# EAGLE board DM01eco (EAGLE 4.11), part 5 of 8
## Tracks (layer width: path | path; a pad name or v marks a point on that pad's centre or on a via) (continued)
DATA_OUT  (via drill 0.61) (continued)
  Bottom 0.152: v22.86,142.24 21.59,143.51 19.68,143.51 1.91,161.29 1.91,164.47 B32.R2 | v250.82,289.56 252.73,289.56 255.91,286.38 259.71,290.19 v270.51,279.4
DATA_OUT0  (via drill 0.61)
  Top 0.152: v10.16,97.79 15.88,103.51 15.88,108.59 17.14,109.86 17.14,110.49 26.67,120.02 26.67,123.19 C30.F2 | v254.63,1.27 269.24,1.27 270.51,2.54 276.86,2.54 307.98,33.66 307.98,36.2 309.25,37.47 D08.M2
  Route2 0.152: v100.33,6.35 104.78,1.91 v132.08,29.21 | v164.47,1.91 165.74,3.18 173.35,3.18 173.99,3.81 187.96,3.81 190.5,1.27 193.68,1.27 194.94,2.54 198.12,2.54 198.75,3.18 200.03,3.18 201.93,5.08 216.53,5.08 218.44,3.18 219.07,3.81 222.88,3.81 226.69,7.62 229.24,7.62 234.31,12.7 235.59,12.7 v236.85,13.97
  Bottom 0.152: v10.16,97.79 7.62,95.25 15.88,87 15.88,80.65 41.27,55.24 41.27,36.2 60.33,17.14 67.31,17.14 70.48,13.97 81.92,13.97 83.19,12.7 93.98,12.7 v100.33,6.35 | v132.08,29.21 132.08,28.58 146.69,13.97 149.86,13.97 154.94,8.89 156.21,8.89 163.19,1.91 v164.47,1.91 | v236.85,13.97 240.03,13.97 252.09,1.91 254,1.91 v254.63,1.27
DATA_OUT1  (via drill 0.61)
  Top 0.152: v241.3,40.64 239.4,40.64 203.2,4.45 203.2,3.81 201.93,2.54 199.39,2.54 v198.75,1.91 | v130.18,41.27 130.18,46.99 v133.35,50.16 | v45.09,133.98 42.55,136.53 27.94,121.92 27.94,118.75 27.3,118.11 C30.J2
  Route15 0.152: v241.3,40.64 243.21,38.73 245.75,38.73 D13.M2 | v198.75,1.91 196.85,1.91 196.22,2.54 191.77,2.54 190.5,1.27 180.34,1.27 179.07,2.54 175.26,2.54 173.99,3.81 168.91,3.81 148.59,24.13 142.88,24.13 132.72,34.29 132.72,34.92 130.18,37.47 v130.18,41.27 | v133.35,50.16 133.35,52.07 123.19,62.23 117.47,62.23 87.63,92.08 87,92.08 v45.09,133.98
DATA_OUT2  (via drill 0.61)
  Top 0.152: v92.08,30.48 95.89,30.48 99.06,33.66 107.31,33.66 108.58,32.38 v109.22,33.02
  Route2 0.152: v132.08,6.35 142.88,6.35 146.05,9.53 151.13,9.53 158.12,16.51 158.12,17.78 160.66,20.32 161.29,20.32 175.26,34.29 176.53,34.29 178.44,36.2 180.97,36.2 182.25,37.47 D18.M2
  Route15 0.152: v57.78,64.77 v92.08,30.48
  Bottom 0.152: v57.78,64.77 49.53,73.03 49.53,78.11 40.64,87 35.56,87 20.95,101.6 26.67,107.32 26.67,110.49 C30.L2 | v109.22,33.02 109.22,32.38 111.76,29.84 116.84,29.84 120.65,26.04 120.65,22.86 119.38,21.59 124.46,16.51 124.46,13.97 v132.08,6.35
DATA_OUT3  (via drill 0.61)
  Top 0.152: v67.94,65.41 67.94,66.04 73.66,71.75 79.38,71.75 v80.01,72.39
  Route15 0.152: v80.01,72.39 81.28,72.39 111.12,42.55 112.39,42.55 114.94,40.01 117.47,40.01 118.75,38.73 D23.M2
  Bottom 0.152: v67.94,65.41 64.14,65.41 63.5,66.04 62.87,66.04 41.27,87.63 41.27,93.34 34.29,100.33 29.21,100.33 27.3,102.23 27.3,104.14 C30.N2
DATA_OUT4  (via drill 0.61)
  Top 0.152: v14.61,81.92 14.61,83.19 26.04,94.62 26.04,97.16 26.67,97.79 C30.R2
  Route15 0.152: v14.61,81.92 55.24,41.27 55.24,38.73 D28.M2
DATA_OUT5  (via drill 0.61)
  Top 0.152: v3.17,136.53 3.17,157.48 15.88,170.18 15.88,175.9 50.16,210.19 50.16,214.63 v55.88,220.34 | v100.33,240.66 102.23,242.57 104.78,242.57 106.05,243.84 A24.M2
  Route2 0.152: v55.88,220.34 54.61,221.62 85.72,252.73 88.27,252.73 v88.9,253.37
  Route15 0.152: v3.17,136.53 3.17,119.38 26.67,95.89 26.67,92.71 C30.T2
  Bottom 0.152: v88.9,253.37 88.9,252.09 v100.33,240.66
DATA_OUT6  (via drill 0.61)
  Top 0.152: v3.17,117.48 3.17,122.56 17.14,136.53 17.78,136.53 21.59,140.34 21.59,142.88 27.94,149.22 33.02,149.22 39.37,155.58 39.37,156.21 41.27,158.12 41.27,163.19 62.23,184.15 v62.87,184.15
  Route15 0.152: v62.87,184.15 62.23,184.15 43.81,202.56 43.81,203.84 53.34,213.36 53.34,216.53 50.8,219.08 50.8,224.79 55.24,229.24 43.81,240.66 43.81,243.21 43.18,243.84 A29.M2
  Bottom 0.152: v3.17,117.48 3.17,113.03 26.67,89.54 26.67,86.36 C30.V2
DB0  (via drill 0.61)
  Top 0.152: v176.53,271.78 183.51,271.78 185.42,269.88 187.96,272.41 189.23,272.41 191.13,274.32 196.22,274.32 200.66,278.76 201.93,278.76 210.82,287.65 213.36,287.65 215.26,289.56 216.53,289.56 v217.17,290.19
  Route2 0.152: v81.28,195.58 81.28,196.85 92.08,207.65 93.98,207.65 100.97,214.63 102.87,214.63 107.95,219.71 116.2,219.71 155.57,259.08 156.21,259.08 162.56,265.43 168.91,265.43 175.26,271.78 v176.53,271.78
  Route15 0.152: v81.28,195.58 81.92,195.58 90.17,187.33 90.17,184.78 B25.J2 | v217.17,290.19 218.44,290.19 219.07,289.56 244.47,289.56 245.11,288.92 250.19,288.92 250.82,288.29 254,288.29 255.91,286.38 257.18,286.38 257.81,285.75 269.24,285.75 271.78,283.21 273.05,283.21 278.13,278.13 279.4,278.13 289.56,267.97 292.74,267.97 293.37,267.33 A09.D2
DB0-0  (via drill 0.61)
  Top 0.152: v274.32,80.01 271.78,80.01 v255.27,63.5
  Route15 0.152: v231.78,85.73 231.78,87 217.81,100.97 217.81,101.6 215.9,103.51 214.63,103.51 212.72,105.41 212.72,106.05 196.85,121.92 193.68,121.92 192.41,123.19 C17.F2
  Bottom 0.152: v274.32,80.01 281.31,73.03 283.21,73.03 285.75,70.48 285.75,69.85 287.02,68.58 288.29,68.58 293.37,63.5 293.37,60.96 D09.D2 | v255.27,63.5 247.65,71.12 246.38,71.12 v231.78,85.73
DB0-1  (via drill 0.61)
  Top 0.152: v237.49,69.85 236.85,69.85 231.78,64.77 231.78,62.23 230.5,60.96 D14.D2
  Route2 0.152: v203.2,104.78 201.93,103.51 200.66,103.51 198.12,100.97 196.22,102.87 196.22,104.78 196.85,105.41 196.85,106.68 203.2,113.03 203.2,113.67 207.01,117.48 205.74,118.75 203.84,118.75 201.93,116.84 200.66,116.84 198.12,114.3 195.58,116.84 192.41,116.84 C17.J2
  Route15 0.152: v203.2,104.78 203.2,103.51 232.41,74.3 233.04,74.3 v237.49,69.85
DB0-2  (via drill 0.61)
  Top 0.152: v201.29,98.43 v165.74,62.87 | v190.5,109.22 191.77,110.49 C17.L2
  Route15 0.152: v165.74,62.87 166.37,62.23 166.37,60.96 D19.D2
  Bottom 0.152: v190.5,109.22 v201.29,98.43
DB0-3  (via drill 0.61)
  Top 0.152: v155.57,79.38 158.75,82.55 166.37,82.55 180.97,97.16 180.97,97.79 182.25,99.06 183.51,99.06 187.96,103.51 191.13,103.51 191.77,104.14 C17.N2
  Route2 0.152: v114.94,45.72 116.2,45.72 117.47,46.99 117.47,52.7 133.35,68.58 133.35,73.03 144.15,83.82 149.22,83.82 v149.86,84.46
  Bottom 0.152: v114.94,45.72 103.5,57.15 103.5,59.69 D24.D2 | v149.86,84.46 150.5,84.46 v155.57,79.38
DB0-4  (via drill 0.61)
  Top 0.152: v99.69,12.7 109.86,12.7 130.81,33.66 131.44,33.66 133.35,35.56 133.35,36.2 v146.69,49.53
  Route2 0.152: v146.69,49.53 152.4,55.24 153.03,55.24 154.31,56.52 154.31,58.42 155.57,59.69 155.57,65.41 187.32,97.16 191.13,97.16 191.77,97.79 C17.R2
  Route15 0.152: v99.69,12.7 99.06,13.34 95.89,13.34 72.39,36.83 66.67,36.83 43.81,59.69 40.01,59.69 D29.D2
DB0-5  (via drill 0.61)
  Top 0.152: v206.38,133.35 206.38,142.88 v207.65,144.15
  Route2 0.152: v215.26,111.12 214.63,111.12 209.55,106.05 209.55,105.41 201.29,97.16 200.66,97.16 196.22,92.71 192.41,92.71 C17.T2
  Route15 0.152: v189.23,163.83 189.23,164.47 186.69,167 185.42,167 184.15,168.28 184.15,170.81 180.97,173.99 179.71,173.99 155.57,198.12 155.57,205.11 154.94,205.74 154.94,210.82 142.24,223.52 137.16,223.52 98.42,262.25 97.16,262.25 94.61,264.8 92.08,264.8 90.81,266.06 A25.D2
  Bottom 0.152: v215.26,111.12 216.53,112.4 217.17,112.4 218.44,113.67 217.17,114.94 217.17,115.57 215.9,116.84 215.9,117.48 214.63,118.75 213.36,118.75 208.28,123.83 207.65,123.83 206.38,125.09 v206.38,133.35 | v207.65,144.15 207.65,146.05 189.87,163.83 v189.23,163.83
DB0-6  (via drill 0.61)
  Route15 0.152: v142.88,139.7 142.88,137.8 175.26,105.41 176.53,105.41 179.71,102.23 179.71,101.6 188.59,92.71 189.23,92.71 v190.5,91.44
  Bottom 0.152: v142.88,139.7 136.53,146.05 136.53,147.32 130.18,153.67 130.18,159.39 128.91,160.66 128.91,161.29 96.52,193.68 96.52,194.31 53.98,236.86 53.98,242.57 30.48,266.06 27.3,266.06 A30.D2 | v190.5,91.44 190.5,89.54 191.13,88.9 191.13,87 191.77,86.36 C17.V2
DB1  (via drill 0.61)
  Top 0.152: v220.98,267.33 221.62,267.33 226.06,271.78 232.41,271.78 233.04,271.14 238.12,271.14 238.76,271.78 243.84,271.78 247.65,275.59 247.65,276.86 v257.81,287.02 | v287.65,258.44 288.93,258.44 289.56,259.08 294.64,259.08 295.27,259.71 295.27,260.99 297.18,262.89 A09.E2
  Route2 0.152: v182.25,252.73 181.61,252.73 160.66,231.78 160.02,231.78 148.59,220.34 142.88,220.34 131.44,208.91 128.27,208.91 127.64,208.28 124.46,208.28 111.12,194.94 111.12,194.31 109.86,193.04 109.22,193.04 94.61,178.44 90.81,178.44 B25.L2 | v190.5,245.75 199.39,245.75 v220.98,267.33
  Bottom 0.152: v182.25,252.73 183.51,252.73 v190.5,245.75 | v257.81,287.02 258.44,287.02 273.05,272.41 273.05,271.78 286.38,258.44 v287.65,258.44
DB1-0  (via drill 0.61)
  Top 0.152: v292.1,53.98 292.1,54.61 294,56.52 296.55,56.52 D09.E2
  Route2 0.152: v231.78,116.84 231.78,118.11 229.87,120.02 227.97,118.11 226.06,118.11 223.52,120.65 222.25,119.38 219.07,119.38 215.26,123.19 214.63,122.56 212.72,122.56 205.1,114.94 205.1,113.67 203.2,111.76 203.2,109.22 204.47,107.95 199.39,102.87 v198.12,102.87
  Route15 0.152: v292.1,53.98 290.83,53.98 275.59,69.22 275.59,73.03 264.8,83.82 260.99,83.82 254.63,90.17 254.63,90.81 253.37,92.08 252.09,92.08 244.47,99.7 238.76,99.7 231.78,106.68 231.78,112.4 232.41,113.03 231.78,113.67 v231.78,116.84
  Bottom 0.152: v198.12,102.87 197.49,102.87 191.77,108.59 191.77,109.22 188.59,112.4 187.96,112.4 180.97,119.38 180.97,121.92 179.71,123.19 C18.F2
DB1-1  (via drill 0.61)
  Top 0.152: v203.84,80.01 203.84,80.65 v208.28,85.09
  Route2 0.152: v231.78,55.24 233.04,56.52 D14.E2
  Bottom 0.152: v231.78,55.24 215.26,71.75 210.19,71.75 204.47,77.47 204.47,79.38 v203.84,80.01 | v208.28,85.09 208.28,85.73 190.5,103.51 189.87,103.51 184.78,108.59 184.15,108.59 182.88,109.86 182.88,111.76 180.97,113.67 180.97,115.57 179.71,116.84 C18.J2
DB1-2  (via drill 0.61)
  Top 0.152: v189.87,78.11 189.23,77.47 189.23,75.57 184.78,71.12 180.97,71.12 173.35,63.5 172.09,63.5 170.18,61.59 170.18,57.78 D19.E2 | v170.18,98.43 170.18,99.06 178.44,107.32 178.44,109.86 179.07,110.49 C18.L2
  Route15 0.152: v189.87,78.11 184.15,83.82 184.15,85.09 v183.51,85.73
  Bottom 0.152: v183.51,85.73 182.88,85.73 v170.18,98.43
DB1-3  (via drill 0.61)
  Top 0.152: v114.3,66.67 113.03,65.41 111.76,65.41 107.31,60.96 107.31,59.05 106.68,58.42 106.68,57.78 D24.E2 | v114.3,77.47 114.3,80.65 124.46,90.81 129.54,90.81 133.35,94.62 133.35,97.16 132.08,98.43 142.88,109.22 148.59,109.22 v153.03,113.67
  Route2 0.152: v168.91,103.51 172.09,106.68 174.62,106.68 177.8,103.51 179.07,104.78 C18.N2
  Route15 0.152: v114.3,66.67 114.3,68.58 118.75,73.03 v114.3,77.47
  Bottom 0.152: v153.03,113.67 154.94,113.67 165.1,103.51 v168.91,103.51
DB1-4  (via drill 0.61)
  Top 0.152: v78.11,78.11 78.11,77.47 66.04,65.41 66.04,64.77 45.72,44.45 41.27,48.89 41.27,51.43 42.55,52.7 42.55,56.52 D29.E2 | v109.86,49.53 109.86,50.8 111.76,52.7 117.47,52.7 133.35,68.58 133.35,73.03 144.15,83.82 149.22,83.82 152.4,80.65 162.56,90.81 168.91,90.81 175.26,97.16 178.44,97.16 179.07,97.79 C18.R2
  Route15 0.152: v78.11,78.11 82.55,78.11 100.97,59.69 101.6,59.69 107.95,53.34 107.95,51.43 v109.86,49.53
DB1-5  (via drill 0.61)
  Route2 0.152: v106.68,166.37 107.31,166.37 117.47,176.53 117.47,179.71 116.2,180.97 142.24,207.01 142.24,209.55 v138.43,213.36
  Route15 0.152: v106.68,166.37 107.31,165.74 107.31,164.47 118.75,153.03 118.75,151.13 130.18,139.7 130.18,138.43 134.62,133.98 134.62,133.35 165.1,102.87 165.1,102.23 170.18,97.16 170.81,97.16 175.26,92.71 179.07,92.71 C18.T2 | v138.43,213.36 134.62,213.36 117.47,230.5 117.47,236.86 94.61,259.71 94.61,262.25 93.98,262.89 A25.E2
DB1-6  (via drill 0.61)
  Top 0.152: v155.57,116.84 155.57,123.19 v157.48,125.09
  Route2 0.152: v183.51,92.08 179.71,88.27 179.71,86.36 C18.V2
  Route15 0.152: v183.51,92.08 182.25,92.08 177.16,97.16 176.53,97.16 174.62,99.06 174.62,99.7 173.99,100.33 168.28,100.33 155.57,113.03 v155.57,116.84 | v157.48,125.09 156.21,125.09 145.41,135.89 145.41,138.43 146.69,139.7 145.41,140.97 143.51,140.97 111.12,173.36 111.12,173.99 109.22,175.9 108.58,175.9 104.78,179.71 104.78,180.34 99.69,185.42 99.06,185.42 95.25,189.23 95.25,189.87 87,198.12 86.36,198.12 81.92,202.56 81.92,205.11 83.19,206.38 63.5,226.06 63.5,226.69 31.75,258.44 31.75,259.71 31.11,260.35 31.11,262.25 30.48,262.89 A30.E2
DB2  (via drill 0.61)
  Top 0.152: v236.85,278.13 246.38,278.13 v255.91,287.65
  Route2 0.152: v236.85,278.13 226.06,278.13 222.25,274.32 216.53,274.32 214.63,272.41 213.36,272.41 212.09,271.14 211.46,271.14 205.1,264.8 205.1,264.16 193.68,252.73 187.32,252.73 163.19,228.6 161.29,230.5 159.38,230.5 148.59,219.71 142.88,219.71 128.27,205.11 127.64,205.11 111.12,188.59 105.41,188.59 104.78,187.96 104.78,182.88 93.98,172.09 90.81,172.09 B25.N2
  Route15 0.152: v282.57,268.6 292.1,259.08 295.27,259.08 296.55,257.81 A09.H2
  Bottom 0.152: v255.91,287.65 259.08,290.83 260.35,290.83 v282.57,268.6
DB2-0  (via drill 0.61)
  Top 0.152: v274.95,26.67 275.59,26.67 296.55,47.62 296.55,50.16 D09.H2
  Route2 0.152: v185.42,119.38 177.8,119.38 175.9,117.48 v175.26,117.48
  Route15 0.152: v249.56,49.53 244.47,49.53 224.79,69.22 224.79,70.48 v223.52,71.75 | v219.07,82.55 219.07,87 186.69,119.38 v185.42,119.38
  Bottom 0.152: v274.95,26.67 273.69,26.67 250.82,49.53 v249.56,49.53 | v223.52,71.75 226.69,74.93 v219.07,82.55 | v175.26,117.48 175.26,118.11 173.99,119.38 168.91,119.38 168.28,120.02 168.28,121.29 166.37,123.19 C19.F2
DB2-1
  Bottom 0.152: C19.J2 167,116.84 170.18,116.84 187.96,99.06 187.96,98.43 189.23,97.16 189.87,97.16 200.66,86.36 200.66,84.46 205.1,80.01 205.1,77.47 209.55,73.03 214.63,73.03 231.14,56.52 231.78,56.52 233.04,55.24 233.04,51.43 D14.H2
DB2-2  (via drill 0.61)
  Top 0.152: v165.74,57.78 163.83,59.69 167.64,63.5 167.64,64.14 187.32,83.82 v187.96,83.82
  Route15 0.152: v165.74,57.78 169.54,53.98 169.54,51.43 D19.H2
  Bottom 0.152: v187.96,83.82 187.96,86.36 184.78,89.54 184.15,89.54 177.8,95.89 177.8,96.52 177.16,97.16 176.53,97.16 175.26,98.43 175.26,99.7 168.28,106.68 168.28,109.22 167,110.49 C19.L2
DB2-3
  Top 0.152: D24.H2 106.05,51.43 106.05,52.07 105.41,52.7 112.39,59.69 113.03,59.69 120.65,67.31 120.65,67.95 124.46,71.75 131.44,71.75 146.05,86.36 146.05,87 149.86,90.81 155.57,90.81 162.56,97.79 162.56,98.43 163.83,99.7 164.47,99.7 165.74,100.97 165.74,103.51 166.37,104.14 C19.N2
DB2-4  (via drill 0.61)
  Top 0.152: v72.39,83.19 43.18,53.98 43.18,51.43 D29.H2 | v83.82,74.93 83.82,75.57 99.06,90.81 104.78,90.81 125.73,111.76 v125.73,112.4
  Route2 0.152: v154.31,89.54 154.94,89.54 162.56,97.16 165.74,97.16 166.37,97.79 C19.R2
  Bottom 0.152: v72.39,83.19 75.56,83.19 v83.82,74.93 | v125.73,112.4 130.18,112.4 144.78,97.79 144.78,97.16 147.96,93.98 148.59,93.98 149.86,92.71 149.86,92.08 151.13,90.81 153.03,90.81 v154.31,89.54
DB2-5  (via drill 0.61)
  Top 0.152: v179.07,106.68 178.44,106.68 173.35,101.6 175.26,99.7 175.26,97.79 170.18,92.71 167,92.71 C19.T2
  Route2 0.152: v74.93,234.31 74.3,234.95 92.08,252.73 92.08,255.27 93.34,256.54 A25.H2
  Route15 0.152: v179.07,106.68 179.07,108.59 140.97,146.69 140.97,149.22 95.25,194.94 95.25,196.22 92.08,199.39 92.08,209.55 88.9,212.72 88.9,220.34 v74.93,234.31
DB2-6  (via drill 0.61)
  Top 0.152: v155.57,80.65 156.21,80.65 158.75,83.19 160.66,83.19 162.56,85.09 166.37,85.09 C19.V2
  Route15 0.152: v142.88,98.43 142.88,99.06 139.7,102.23 139.7,103.51 92.08,151.13 88.9,151.13 82.55,157.48 82.55,158.12 75.56,165.1 76.83,166.37 76.83,168.91 42.55,203.2 44.45,205.11 44.45,207.01 48.26,210.82 48.26,222.89 43.18,227.97 44.45,229.24 44.45,232.41 41.27,235.59 41.27,242.57 30.48,253.37 30.48,256.54 A30.H2 | v142.88,92.08 144.15,92.08 v155.57,80.65
  Bottom 0.152: v142.88,98.43 142.88,97.79 140.34,95.25 142.88,92.71 v142.88,92.08
DB3  (via drill 0.61)
  Route2 0.152: v157.48,223.52 153.03,219.08 142.88,219.08 133.35,209.55 133.35,205.74 130.18,202.56 130.18,195.58 107.31,172.72 101.6,172.72 94.61,165.74 90.81,165.74 B25.R2 | v168.91,220.98 175.26,227.33 181.61,227.33 194.94,240.66 194.94,241.3 198.75,245.11 199.39,245.11 203.2,248.92 208.91,248.92 231.78,271.78 231.78,272.41 233.04,273.69 236.22,270.51 236.85,271.14 237.49,271.14 238.76,272.41 240.03,272.41 245.11,277.5 248.92,277.5 254,282.57 257.18,282.57 260.35,285.75 263.52,285.75 264.8,287.02 269.88,287.02 271.14,288.29 271.78,288.29 276.23,283.84 v274.95,282.57
  Bottom 0.152: v157.48,223.52 160.02,226.06 165.1,220.98 v168.91,220.98 | v274.95,282.57 274.95,281.3 278.13,278.13 278.76,278.13 295.27,261.62 295.27,252.73 296.55,251.46 A09.K2
DB3-0  (via drill 0.61)
  Top 0.152: v177.8,123.19 182.88,118.11 187.32,122.56 194.31,122.56 197.49,125.73 200.03,125.73 201.29,124.46 v201.93,125.09
  Route2 0.152: v173.35,127 168.91,122.56 162.56,122.56 160.66,120.65 158.12,123.19 154.31,123.19 C20.F2
  Route15 0.152: v173.35,127 175.9,124.46 176.53,124.46 v177.8,123.19 | v215.9,115.57 216.53,115.57 228.6,103.51 228.6,102.23 236.85,93.98 237.49,93.98 276.23,55.24 283.21,55.24 292.1,46.35 295.27,46.35 296.55,45.09 D09.K2
  Bottom 0.152: v201.93,125.09 205.74,125.09 211.46,119.38 212.09,119.38 213.36,118.11 213.36,117.48 214.63,116.21 215.26,116.21 v215.9,115.57
DB3-1  (via drill 0.61)
  Top 0.152: v183.51,82.55 179.07,82.55 v174.62,78.11 | v155.57,107.32 155.57,115.57 154.31,116.84 C20.J2
  Route2 0.152: v152.4,98.43 152.4,100.97 155.57,104.14 v155.57,107.32
  Bottom 0.152: v183.51,82.55 194.31,71.75 196.85,71.75 200.66,67.95 205.74,67.95 211.46,62.23 212.09,62.23 229.24,45.09 233.04,45.09 D14.K2 | v174.62,78.11 174.62,80.01 165.1,89.54 165.1,90.17 158.75,96.52 153.67,96.52 152.4,97.79 v152.4,98.43
DB3-2  (via drill 0.61)
  Top 0.152: v157.48,103.51 159.38,101.6 156.21,98.43 156.21,97.79 151.76,93.34 151.13,93.34 149.22,91.44 149.22,90.81 v135.25,76.84
  Bottom 0.152: v157.48,103.51 154.31,106.68 154.31,110.49 C20.L2 | v135.25,76.84 135.25,76.2 165.1,46.35 168.28,46.35 169.54,45.09 D19.K2
DB3-3  (via drill 0.61)
  Top 0.152: v142.24,95.89 149.86,103.51 153.03,103.51 153.67,104.14 C20.N2
  Route2 0.152: v101.6,58.42 100.33,59.69 102.23,61.59 104.14,61.59 106.05,59.69 117.47,71.12 121.28,71.12 126.36,76.2 126.36,78.74 130.81,83.19 130.81,85.73 133.99,88.9 135.25,88.9 v142.24,95.89
  Bottom 0.152: v101.6,58.42 104.78,55.24 104.78,50.16 106.05,48.89 106.05,45.09 D24.K2
DB3-4  (via drill 0.61)
  Top 0.152: v73.66,22.23 74.3,22.23 109.86,57.78 v109.86,58.42
  Route2 0.152: v109.86,58.42 111.12,58.42 112.39,59.69 113.03,59.69 114.3,60.96 114.3,62.23 137.16,85.09 137.16,85.73 138.43,87 139.7,87 149.86,97.16 153.03,97.16 153.67,97.79 C20.R2
  Bottom 0.152: v73.66,22.23 73.66,22.86 53.98,42.55 48.26,42.55 46.99,43.81 43.18,43.81 D29.K2
DB3-5  (via drill 0.61)
  Top 0.152: v122.56,139.7 124.46,141.61 128.91,141.61 137.79,150.5 137.79,152.4 142.88,157.48 142.88,163.19 v158.75,179.07
  Route2 0.152: v117.47,133.35 117.47,134.62 v122.56,139.7
  Route15 0.152: v144.15,99.7 144.78,99.06 144.78,97.16 146.05,95.89 146.69,95.89 149.22,93.34 151.13,93.34 151.76,92.71 153.67,92.71 C20.T2 | v158.75,179.07 158.75,181.61 154.31,186.06 154.31,187.96 152.4,189.87 152.4,192.41 153.67,193.68 97.79,249.56 94.61,249.56 93.98,250.19 A25.K2
  Bottom 0.152: v144.15,99.7 143.51,99.7 117.47,125.73 v117.47,133.35
DB3-6  (via drill 0.61)
  Top 0.152: v141.6,163.19 141.6,161.93 132.72,153.03 132.72,147.96 v130.81,146.05 | v168.91,104.78 172.09,101.6 167.64,97.16 162.56,97.16 155.57,90.17 155.57,87.63 154.31,86.36 C20.V2
  Route15 0.152: v141.6,163.19 140.97,163.83 139.7,163.83 110.49,193.04 109.86,193.04 104.78,198.12 104.78,204.47 99.69,209.55 99.69,214.63 92.08,222.25 92.08,223.52 69.22,246.38 63.5,246.38 54.61,255.27 48.26,255.27 41.91,261.62 35.56,261.62 30.48,266.7 28.57,264.8 28.57,256.54 29.84,255.27 29.84,251.46 A30.K2 | v130.81,146.05 130.81,144.15 150.5,124.46 151.13,124.46 158.75,116.84 158.75,116.21 163.19,111.76 163.83,111.76 165.1,110.49 165.1,108.59 v168.91,104.78
DB4  (via drill 0.61)
  Top 0.152: v82.55,161.93 83.82,161.93 92.08,170.18 92.08,182.25 102.87,193.04 102.87,194.31 v108.58,200.03 | v114.3,205.11 114.3,205.74 114.94,206.38 114.94,210.19 v127,222.25
  Route2 0.152: v108.58,200.03 109.22,200.03 v114.3,205.11 | v127,222.25 127,223.52 137.16,233.68 143.51,233.68 149.86,240.03 155.57,240.03 180.34,264.8 180.97,264.8 187.96,271.78 193.68,271.78 200.66,278.76 205.74,278.76 v215.26,288.29
  Route15 0.152: v215.26,288.29 236.22,288.29 236.85,287.65 242.57,287.65 243.21,287.02 244.47,287.02 247.01,284.48 260.99,284.48 273.05,272.41 273.05,271.78 292.1,252.73 292.1,251.46 295.27,248.28 295.27,246.38 296.55,245.11 A09.M2
  Bottom 0.152: v82.55,161.93 83.19,161.29 85.09,161.29 87,159.39 90.17,159.39 B25.T2
DB4-0  (via drill 0.61)
  Top 0.152: v248.28,20.32 244.47,20.32 236.85,12.7 231.14,12.7 223.52,5.08 v220.34,5.08 | v173.35,49.53 172.09,49.53 141.6,19.05 141.6,18.41 132.72,9.53 127.64,9.53 v125.73,7.62
  Route2 0.152: v268.61,6.35 296.55,34.29 296.55,37.47 D09.M2 | v76.2,60.32 76.2,62.23 82.55,68.58 82.55,72.39 85.09,74.93 85.09,77.47 95.25,87.63 95.25,90.17 90.17,95.25 104.78,109.86 104.78,115.57 114.3,125.09 118.11,125.09 122.56,120.65 132.08,130.18 139.7,122.56 140.97,123.83 C21.F2
  Route15 0.152: v220.34,5.08 219.71,5.08 215.9,8.89 214.63,8.89 173.99,49.53 v173.35,49.53 | v125.73,7.62 120.65,7.62 107.95,20.32 107.95,21.59 104.78,24.77 104.78,29.84 105.41,30.48 104.78,31.12 104.78,35.56 104.14,36.2 99.06,36.2 76.2,59.05 v76.2,60.32
  Bottom 0.152: v268.61,6.35 261.62,6.35 248.28,19.69 v248.28,20.32
DB4-1  (via drill 0.61)
  Top 0.152: v114.3,85.09 114.3,86.36 120.65,92.71 120.65,93.98 136.53,109.86 136.53,110.49 138.43,112.4 139.06,112.4 140.97,114.3 140.97,116.84 C21.J2 | v208.91,34.92 208.91,35.56 218.44,45.09 v219.07,45.09
  Route2 0.152: v146.05,63.5 147.96,63.5 149.86,65.41 v150.5,65.41 | v192.41,26.67 193.68,26.67 203.2,36.2 207.65,36.2 v208.91,34.92
  Route15 0.152: v114.3,85.09 114.94,84.46 119.38,84.46 128.27,75.57 129.54,75.57 137.16,67.95 142.24,67.95 146.05,64.14 v146.05,63.5 | v150.5,65.41 151.76,65.41 168.28,48.89 168.28,43.18 177.8,33.66 184.15,33.66 190.5,27.3 191.77,27.3 v192.41,26.67
  Bottom 0.152: v219.07,45.09 220.98,46.99 228.6,39.37 232.41,39.37 233.04,38.73 D14.M2
DB4-2  (via drill 0.61)
  Top 0.152: v188.59,59.69 170.18,41.27 170.18,38.73 D19.M2
  Bottom 0.152: v188.59,59.69 188.59,60.32 183.51,65.41 182.88,65.41 177.8,70.48 177.8,71.12 151.76,97.16 151.13,97.16 149.86,98.43 149.86,99.7 142.88,106.68 142.88,109.22 141.6,110.49 C21.L2
DB4-3  (via drill 0.61)
  Top 0.152: v93.98,55.24 94.61,55.24 116.2,76.84 116.2,77.47 122.56,83.82 123.19,83.82 137.16,97.79 137.16,98.43 138.43,99.7 139.06,99.7 140.34,100.97 140.34,103.51 140.97,104.14 C21.N2
  Bottom 0.152: v93.98,55.24 94.61,54.61 94.61,53.34 102.87,45.09 101.6,43.81 101.6,40.64 103.5,38.73 106.05,38.73 D24.M2
DB4-4  (via drill 0.61)
  Top 0.152: v58.42,20.32 59.69,20.32 81.92,42.55 81.92,43.18 v84.45,45.72
  Route2 0.152: v84.45,45.72 85.72,45.72 101.6,61.59 101.6,62.87 122.56,83.82 123.19,83.82 136.53,97.16 140.34,97.16 140.97,97.79 C21.R2
  Bottom 0.152: v58.42,20.32 57.78,20.32 43.18,34.92 43.18,37.47 D29.M2
DB4-5  (via drill 0.61)
  Top 0.152: v117.47,259.08 110.49,252.09 109.86,252.09 104.14,246.38 99.06,246.38 97.79,245.11 93.98,245.11 A25.M2 | v142.88,126.37 142.88,122.56 v128.91,108.59
  Route2 0.152: v151.76,212.72 151.76,211.46 139.7,199.39 139.7,198.75 120.65,179.71 120.65,178.44 120.02,177.8 120.02,177.16 118.75,175.9 117.47,175.9 106.68,165.1 102.87,168.91 104.78,170.81 v104.78,171.45
  Route15 0.152: v104.78,171.45 106.05,171.45 124.46,153.03 124.46,149.86 142.88,131.44 v142.88,126.37 | v128.91,108.59 128.91,107.32 137.16,99.06 137.16,98.43 138.43,97.16 139.06,97.16 140.34,95.89 140.34,93.34 140.97,92.71 C21.T2
  Bottom 0.152: v117.47,259.08 117.47,248.92 130.18,236.22 130.18,230.5 137.16,223.52 142.24,223.52 151.76,214 v151.76,212.72
DB4-6  (via drill 0.61)
  Top 0.152: v130.81,76.84 132.72,76.84 140.97,85.09 C21.V2
  Route15 0.152: v60.96,152.4 60.96,153.03 41.27,172.72 41.27,179.07 33.02,187.33 38.73,193.04 38.73,194.31 30.48,202.56 30.48,203.2 28.57,205.11 28.57,229.87 20.32,238.12 26.04,243.84 29.84,243.84 A30.M2 | v102.23,108.59 102.87,108.59 118.11,93.34 118.11,90.17 116.84,88.9 120.65,85.09 120.65,84.46 125.73,79.38 128.27,79.38 v130.81,76.84
  Bottom 0.152: v60.96,152.4 60.96,144.78 69.85,135.89 69.85,135.25 70.48,134.62 72.39,134.62 74.3,136.53 79.38,131.44 79.38,125.73 99.06,106.05 100.97,106.05 102.87,107.95 v102.23,108.59
DB5  (via drill 0.61)
  Top 0.152: v210.82,277.5 v224.16,290.83
  Route2 0.152: v176.53,287.02 168.91,279.4 163.19,279.4 148.59,264.8 147.96,264.8 144.78,261.62 140.34,261.62 138.43,259.71 137.16,259.71 117.47,240.03 111.76,240.03 95.25,223.52 95.25,222.89 79.38,207.01 79.38,202.56 78.11,201.3 78.11,197.49 B26.D2
  Route15 0.152: v257.18,279.4 259.08,279.4 264.16,274.32 269.88,274.32 282.57,261.62 v282.57,260.35
  Bottom 0.152: v176.53,287.02 201.29,287.02 v210.82,277.5 | v224.16,290.83 243.21,290.83 245.11,288.92 246.38,288.92 250.19,285.11 251.46,285.11 v257.18,279.4 | v282.57,260.35 282.57,255.91 289.56,248.92 294.64,248.92 295.27,248.28 295.27,240.03 296.55,238.76 A09.P2
DB5-0  (via drill 0.61)
  Route2 0.152: v193.68,66.67 195.58,66.67 200.66,71.75 204.47,71.75 205.1,72.39 215.9,72.39 v216.53,73.03
  Route15 0.152: v193.68,66.67 193.68,67.31 193.04,67.95 187.96,67.95 175.26,80.65 175.26,86.36 170.81,90.81 165.1,90.81 157.48,98.43 158.75,99.7 158.75,103.51 157.48,104.78 156.84,104.78 148.59,113.03 147.96,113.03 142.24,118.75 137.16,118.75 132.72,123.19 128.91,123.19 C22.F2 | v216.53,73.03 218.44,74.93 250.82,42.55 257.81,42.55 276.86,23.5 283.21,23.5 289.56,17.14 292.1,17.14 300.36,25.4 297.81,27.94 297.81,30.48 297.18,31.12 D09.P2
DB5-1  (via drill 0.61)
  Top 0.152: v177.8,73.03 181.61,73.03 183.51,74.93 184.15,74.93 v184.78,74.3
  Route15 0.152: v177.8,73.03 177.16,73.03 163.83,86.36 162.56,86.36 151.76,97.16 151.13,97.16 149.86,98.43 149.86,99.06 139.06,109.86 138.43,109.86 137.16,111.12 137.16,111.76 132.08,116.84 128.91,116.84 C22.J2 | v184.78,74.3 187.32,74.3 201.93,59.69 v203.2,59.69
  Bottom 0.152: v203.2,59.69 203.2,59.05 215.9,46.35 216.53,46.35 222.25,40.64 222.25,40.01 228.6,33.66 231.78,33.66 233.04,32.38 D14.P2
DB5-2  (via drill 0.61)
  Route2 0.152: v121.28,89.54 120.02,90.81 120.02,92.71 130.18,102.87 130.18,109.22 128.91,110.49 C22.L2
  Route15 0.152: v121.28,89.54 124.46,86.36 124.46,85.09 125.73,83.82 127,83.82 165.74,45.09 165.74,42.55 164.47,41.27 165.1,40.64 165.1,38.73 168.28,35.56 168.28,33.66 169.54,32.38 D19.P2
DB5-3  (via drill 0.61)
  Top 0.152: v118.75,109.86 118.75,110.49 v123.19,114.94
  Route2 0.152: v118.75,109.86 117.47,108.59 117.47,97.16 98.42,78.11 98.42,76.2 97.16,74.93 97.16,71.12 88.9,62.87 88.9,61.59 78.11,50.8 86.36,42.55 88.27,42.55 90.17,44.45 102.23,32.38 106.05,32.38 D24.P2
  Route15 0.152: v123.19,114.94 123.19,113.03 127.64,108.59 127.64,106.05 128.27,105.41 C22.N2
DB5-4  (via drill 0.61)
  Top 0.152: v64.77,56.52 53.98,45.72 53.98,40.64 53.34,40.01 48.26,40.01 43.18,34.92 43.18,32.38 D29.P2 | v95.89,71.75 97.16,71.75 107.95,82.55 115.57,82.55 127.64,94.62 127.64,97.16 128.27,97.79 C22.R2
  Route2 0.152: v64.77,56.52 71.12,50.16 79.38,58.42 79.38,59.05 85.72,65.41 87,65.41 92.71,71.12 95.25,71.12 v95.89,71.75
DB5-5  (via drill 0.61)
  Top 0.152: v72.39,215.9 72.39,219.71 88.9,236.22 92.08,236.22 93.34,237.49 A25.P2
  Route2 0.152: v128.91,95.89 128.91,92.71 C22.T2 | v88.9,149.22 88.9,154.94 92.08,158.12 92.08,160.66 84.45,168.28 v93.34,177.16
  Route15 0.152: v128.91,95.89 132.08,99.06 125.09,106.05 124.46,106.05 120.02,110.49 120.02,111.76 121.92,113.67 121.92,114.94 117.47,119.38 117.47,124.46 116.84,125.09 111.76,125.09 110.49,126.37 110.49,127.64 v109.86,128.27 | v93.34,177.16 93.34,177.8 85.09,186.06 84.45,186.06 78.74,191.77 78.74,195.58 80.01,196.85 79.38,197.49 79.38,208.91 v72.39,215.9
  Bottom 0.152: v109.86,128.27 110.49,128.27 112.39,130.18 110.49,132.08 105.41,132.08 104.78,132.72 104.78,137.8 100.97,141.61 96.52,141.61 v88.9,149.22
DB5-6  (via drill 0.61)
  Top 0.152: v107.31,66.67 107.31,67.31 111.76,71.75 123.19,71.75 129.54,78.11 129.54,81.92 127.64,83.82 128.91,85.09 C22.V2
  Route2 0.152: v3.81,202.56 14.61,213.36 14.61,214.63 18.41,218.44 18.41,222.89 29.84,234.31 29.84,237.49 A30.P2
  Route15 0.152: v31.75,155.58 31.75,153.03 25.4,146.69 33.66,138.43 34.29,138.43 53.98,118.75 v53.98,114.94
  Bottom 0.152: v3.81,202.56 1.27,200.03 3.17,198.12 3.17,191.77 15.88,179.07 15.88,173.36 29.84,159.39 29.84,158.12 31.75,156.21 v31.75,155.58 | v53.98,114.94 53.98,113.67 54.61,113.03 59.69,113.03 79.38,93.34 79.38,87.63 83.19,83.82 93.98,83.82 98.42,79.38 98.42,75.57 v107.31,66.67
DB6  (via drill 0.61)
  Top 0.152: v241.3,235.59 241.3,236.22 254,248.92 259.71,248.92 265.43,254.64 v265.43,255.27
  Route2 0.152: v139.7,259.71 139.06,259.08 137.16,259.08 111.12,233.05 105.41,233.05 104.78,232.41 104.78,227.33 96.52,219.08 92.08,219.08 88.9,215.9 88.9,213.36 82.55,207.01 82.55,205.11 79.38,201.93 79.38,196.22 78.11,194.94 78.11,191.14 B26.F2 | v207.65,201.93 207.65,202.56 240.66,235.59 v241.3,235.59
  Route15 0.152: v139.7,259.71 139.7,259.08 146.69,252.09 149.22,252.09 151.13,254 180.34,224.79 180.34,223.52 191.13,212.72 191.13,212.09 193.68,209.55 195.58,209.55 203.2,201.93 v207.65,201.93 | v265.43,255.27 270.51,255.27 278.13,247.65 278.76,247.65 280.04,246.38 280.04,245.11 290.83,234.31 v290.83,233.68
  Bottom 0.152: v290.83,233.68 295.27,233.68 296.55,232.41 A09.S2
DB6-0  (via drill 0.61)
  Top 0.152: v209.55,1.91 209.55,2.54 217.81,10.79 219.71,10.79 v222.25,13.34
  Route2 0.152: v123.19,101.6 123.83,102.23 123.83,103.51 128.27,107.95 116.2,120.02 116.2,123.19 C23.F2 | v245.75,1.91 247.01,1.91 247.65,2.54 262.25,2.54 263.52,3.81 269.88,3.81 271.14,5.08 273.69,5.08 292.1,23.5 295.27,23.5 296.55,24.77 D09.S2
  Route15 0.152: v133.99,87.63 132.08,85.73 133.99,83.82 142.88,83.82 v144.15,82.55 | v173.35,43.18 173.99,43.18 180.97,36.2 v180.97,34.92
  Bottom 0.152: v123.19,101.6 123.19,100.97 127,97.16 128.91,97.16 130.18,95.89 130.18,93.98 130.81,93.34 130.81,92.08 133.35,89.54 133.35,88.27 v133.99,87.63 | v144.15,82.55 146.05,82.55 149.22,79.38 149.22,74.93 159.38,64.77 160.02,64.77 161.29,63.5 161.29,62.23 162.56,60.96 162.56,59.05 160.66,57.15 165.1,52.7 165.1,51.43 v173.35,43.18 | v180.97,34.92 180.97,30.48 v209.55,1.91 | v222.25,13.34 228.6,13.34 238.12,3.81 243.84,3.81 v245.75,1.91
DB6-1  (via drill 0.61)
  Top 0.152: v220.34,15.88 v231.78,27.3
  Route15 0.152: v231.78,27.3 233.04,26.04 D14.S2 | v220.34,15.88 212.09,24.13 207.01,24.13 203.2,27.94 v203.2,28.58 | v171.45,59.05 170.81,59.05 139.06,90.81 v138.43,90.81
  Bottom 0.152: v203.2,28.58 201.93,28.58 196.22,34.29 196.22,34.92 188.59,42.55 187.96,42.55 v171.45,59.05 | v138.43,90.81 138.43,91.44 129.54,100.33 129.54,102.87 131.44,104.78 120.65,115.57 117.47,115.57 116.2,116.84 C23.J2
DB6-2  (via drill 0.61)
  Route2 0.152: v125.09,76.2 125.09,78.11 130.18,83.19 v130.18,89.54
  Bottom 0.152: v125.09,76.2 130.18,71.12 133.35,71.12 137.79,66.67 135.89,64.77 135.89,62.87 137.16,61.59 137.79,61.59 144.15,55.24 144.15,54.61 149.86,48.89 150.5,48.89 153.03,46.35 153.03,45.72 169.54,29.21 169.54,26.04 D19.S2 | v130.18,89.54 130.18,93.34 120.65,102.87 120.65,104.14 117.47,107.32 117.47,109.22 116.2,110.49 C23.L2
DB6-3  (via drill 0.61)
  Top 0.152: v147.32,68.58 146.69,68.58 107.95,29.84 107.95,29.21 106.68,27.94 106.68,26.04 D24.S2
  Bottom 0.152: v147.32,68.58 147.32,69.22 142.88,73.66 142.24,73.66 131.44,84.46 131.44,85.73 118.75,98.43 118.75,99.7 117.47,100.97 117.47,102.87 116.2,104.14 C23.N2
DB6-4
  Top 0.152: D29.S2 43.18,26.04 43.18,29.21 76.83,62.87 76.83,65.41 75.56,66.67 76.83,67.95 81.28,67.95 82.55,69.22 82.55,71.75 85.72,74.93 85.72,76.2 92.08,82.55 102.87,82.55 114.94,94.62 114.94,97.16 115.57,97.79 C23.R2
DB6-5  (via drill 0.61)
  Route2 0.152: v55.24,179.07 53.98,180.34 53.98,182.25 92.08,220.34 92.08,226.06 93.34,227.33 93.34,231.14 A25.S2
  Bottom 0.152: v55.24,179.07 55.24,177.8 66.67,166.37 66.67,154.94 67.31,154.31 72.39,154.31 73.66,153.03 74.93,153.03 76.83,151.13 78.74,151.13 92.08,137.8 92.08,130.81 97.16,125.73 97.79,125.73 104.78,118.75 104.78,111.76 107.95,108.59 107.95,105.41 106.68,104.14 114.94,95.89 114.94,93.34 115.57,92.71 C23.T2
DB6-6
  Route15 0.152: C23.V2 115.57,86.36 115.57,88.9 95.25,109.22 95.25,110.49 92.08,113.67 92.08,125.09 75.56,141.61 73.03,141.61 53.98,160.66 53.98,167 41.27,179.71 41.27,192.41 31.11,202.56 31.11,204.47 33.66,207.01 33.66,214.63 32.38,215.9 32.38,217.81 36.83,222.25 31.11,227.97 31.11,230.5 30.48,231.14 A30.S2
DB7  (via drill 0.61)
  Top 0.152: v92.08,194.31 91.44,194.31 85.72,188.59 84.45,188.59 80.64,184.78 78.11,184.78 B26.J2 | v116.84,215.27 116.84,220.34 153.03,256.54 153.03,259.08 151.13,260.99 155.57,265.43 155.57,271.14 162.56,278.13 v163.83,278.13 | v235.59,210.19 244.47,219.08 254.63,219.08 v255.91,220.34 | v276.23,209.55 277.5,209.55 292.74,224.79 292.74,227.33 293.37,227.97 A09.T2
  Route2 0.152: v92.08,194.31 92.08,194.94 99.06,201.93 104.14,201.93 116.84,214.63 v116.84,215.27
  Route15 0.152: v163.83,278.13 164.47,278.13 198.75,243.84 199.39,243.84 222.88,220.34 225.43,220.34 v235.59,210.19 | v255.91,220.34 265.43,220.34 v276.23,209.55
DB7-0  (via drill 0.61)
  Top 0.152: v191.77,96.52 190.5,97.79 190.5,99.06 191.13,99.7 195.58,99.7 196.85,100.97 196.85,102.87 195.58,104.14 v194.94,103.51
  Route2 0.152: v167.64,126.37 160.66,133.35 152.4,125.09 149.22,125.09 140.97,133.35 139.06,131.44 137.16,131.44 132.08,136.53 130.81,136.53 129.54,135.25 124.46,135.25 118.11,128.91 118.11,128.27 116.84,127 115.57,127 110.49,121.92 104.78,121.92 103.5,123.19 C24.F2
  Route15 0.152: v191.77,96.52 196.85,96.52 207.01,86.36 207.01,83.82 208.28,82.55 212.72,82.55 219.07,76.2 220.98,76.2 224.16,73.03 227.97,73.03 232.41,68.58 237.49,68.58 279.4,26.67 285.75,26.67 289.56,22.86 293.37,22.86 D09.T2 | v194.94,103.51 194.94,104.78 193.68,106.05 187.96,106.05 186.06,107.95 184.78,107.95 182.88,109.86 182.88,111.12 v167.64,126.37
DB7-1  (via drill 0.61)
  Top 0.152: v212.09,3.81 214,3.81 224.16,13.97 224.79,13.97 229.24,18.41 229.24,20.95 229.87,21.59 D14.T2
  Route15 0.152: v182.25,35.56 147.96,69.85 146.69,69.85 145.41,71.12 144.78,71.12 130.18,85.73 130.18,87 103.5,113.67 103.5,116.84 C24.J2
  Bottom 0.152: v182.25,35.56 203.84,13.97 204.47,13.97 205.74,12.7 205.74,10.16 v212.09,3.81
DB7-2  (via drill 0.61)
  Top 0.152: v168.28,29.21 168.28,24.13 167,22.86 D19.T2
  Route15 0.152: v142.88,57.78 142.88,56.52 146.05,53.34 146.05,52.7 151.13,47.62 151.76,47.62 158.75,40.64 158.75,40.01 160.02,38.73 v156.21,34.92
  Bottom 0.152: v142.88,57.78 142.88,67.31 142.24,67.95 137.16,67.95 132.72,72.39 130.18,72.39 121.92,80.65 119.38,80.65 118.11,81.92 118.11,86.36 104.78,99.7 104.78,105.41 103.5,106.68 103.5,110.49 C24.L2 | v156.21,34.92 157.48,34.92 162.56,29.84 167.64,29.84 v168.28,29.21
DB7-3  (via drill 0.61)
  Top 0.152: v106.68,29.21 103.5,26.04 103.5,22.86 D24.T2 | v65.41,69.22 65.41,69.85 99.06,103.51 102.23,103.51 102.87,104.14 C24.N2
  Bottom 0.152: v106.68,29.21 104.14,31.75 102.87,31.75 v65.41,69.22
DB7-4  (via drill 0.61)
  Top 0.152: v85.09,70.48 53.98,39.37 53.98,33.66 43.18,22.86 40.01,22.86 D29.T2 | v82.55,74.3 82.55,74.93 99.06,91.44 99.06,92.08 100.33,93.34 100.97,93.34 102.23,94.62 102.23,97.16 102.87,97.79 C24.R2
  Bottom 0.152: v85.09,70.48 85.09,71.75 v82.55,74.3
DB7-5  (via drill 0.61)
  Top 0.152: v78.11,126.37 78.11,127.64 89.53,139.06 v89.53,146.05 | v71.75,163.19 72.39,163.19 83.19,173.99 83.19,174.62 84.45,175.9 85.09,175.9 92.08,182.88 92.08,187.96 92.71,188.59 93.98,188.59 95.25,189.87 94.61,190.5 95.25,191.14 95.25,191.77 95.89,192.41 97.79,192.41 99.06,191.14 v99.69,191.77 | v80.01,217.81 80.01,220.98 86.36,227.33 89.53,227.33 90.17,227.97 A25.T2
  Route2 0.152: v104.78,94.62 103.5,93.34 103.5,92.71 C24.T2
  Bottom 0.152: v104.78,94.62 104.78,99.06 101.6,102.23 101.6,102.87 v78.11,126.37 | v89.53,146.05 88.9,146.05 87.63,147.32 86.36,147.32 72.39,161.29 72.39,162.56 v71.75,163.19 | v99.69,191.77 100.97,191.77 106.05,196.85 97.79,205.11 92.71,205.11 v80.01,217.81
DB7-6  (via drill 0.61)
  Top 0.152: v15.88,214.63 26.67,225.43 26.67,227.97 A30.T2
  Route15 0.152: v66.67,133.98 66.67,125.73 87.63,104.78 v88.27,104.78
  Bottom 0.152: v15.88,214.63 15.88,210.19 19.05,207.01 19.05,203.84 15.24,200.03 15.24,198.12 15.88,197.49 15.88,192.41 52.07,156.21 52.07,154.94 53.98,153.03 53.98,151.13 63.5,141.61 63.5,140.34 66.67,137.16 v66.67,133.98 | v88.27,104.78 88.27,103.51 93.34,98.43 93.34,97.79 95.25,95.89 95.25,93.34 93.98,92.08 99.06,87 102.23,87 102.87,86.36 C24.V2
DB8  (via drill 0.61)
  Route2 0.152: v97.79,193.68 96.52,192.41 95.25,192.41 81.28,178.44 78.11,178.44 B26.L2 | v98.42,214.63 145.41,261.62 146.05,261.62 152.4,267.97 158.12,267.97 162.56,272.41 163.83,272.41 165.74,274.32 170.81,274.32 174.62,278.13 181.61,278.13 v193.68,290.19 | v274.95,217.17 288.93,217.17 293.37,221.62 A09.V2
  Route15 0.152: v97.79,193.68 97.79,194.94 102.87,200.03 98.42,204.47 98.42,205.74 97.79,206.38 97.79,212.72 99.06,214 v98.42,214.63 | v237.49,257.18 237.49,255.91 273.69,219.71 273.69,218.44 v274.95,217.17
  Bottom 0.152: v193.68,290.19 203.84,290.19 222.88,271.14 225.43,271.14 227.33,273.05 238.12,262.25 238.12,260.99 238.76,260.35 238.76,259.71 236.85,257.81 v237.49,257.18
DB8-0  (via drill 0.61)
  Route2 0.152: v117.47,21.59 116.84,20.95 111.12,20.95 107.31,17.14 102.23,17.14 100.33,15.24 75.56,40.01 73.03,40.01 68.58,35.56 62.23,41.91 64.77,44.45 50.8,58.42 50.8,60.96 53.98,64.14 53.98,79.38 56.52,81.92 56.52,86.36 61.59,91.44 61.59,92.08 90.17,120.65 90.17,123.19 C25.F2 | v155.57,6.99 156.21,6.99 158.12,8.89 191.77,8.89 193.68,10.79 206.38,10.79 207.65,12.07 210.82,12.07 216.53,17.78 222.25,17.78 226.06,21.59 227.33,21.59 233.04,27.3 233.04,28.58 240.03,35.56 v240.03,36.2
  Route15 0.152: v117.47,21.59 120.02,21.59 132.08,9.53 153.03,9.53 v155.57,6.99 | v240.03,36.2 245.11,36.2 251.46,29.84 257.81,29.84 264.16,23.5 270.51,23.5 276.86,17.14 283.21,17.14 286.38,13.97 292.1,13.97 293.37,15.24 D09.V2
DB8-1  (via drill 0.61)
  Top 0.152: v172.09,20.32 168.91,20.32 165.1,16.51 165.1,14.61 154.31,3.81 v151.13,6.99
  Route2 0.152: v189.23,6.35 189.87,6.99 214.63,6.99 218.44,10.79 219.07,10.79 219.71,11.43 224.16,11.43 227.97,15.24 229.87,15.24 D14.V2 | v151.13,6.99 147.32,6.99 146.69,6.35 144.78,6.35 143.51,5.08 v124.46,5.08 | v74.93,55.24 73.03,55.24 67.94,60.32 76.83,69.22 76.83,70.48 90.81,84.46 91.44,84.46 92.08,85.09 92.08,92.71 89.53,95.25 92.08,97.79 92.08,115.57 90.81,116.84 C25.J2
  Bottom 0.152: v189.23,6.35 186.06,6.35 v172.09,20.32 | v124.46,5.08 117.47,5.08 101.6,20.95 101.6,24.77 102.87,26.04 94.61,34.29 94.61,34.92 87,42.55 86.36,42.55 81.92,46.99 81.92,49.53 83.19,50.8 78.74,55.24 v74.93,55.24
DB8-2  (via drill 0.61)
  Top 0.152: v76.2,98.43 76.2,99.7 86.36,109.86 87.63,109.86 88.27,110.49 90.17,110.49 C25.L2 | v146.05,1.91 146.69,1.91 147.96,3.18 154.31,3.18 166.37,15.24 D19.V2
  Route15 0.152: v76.2,98.43 76.2,97.16 78.11,95.25 78.11,93.98 84.45,87.63 85.09,87.63 86.36,86.36 86.36,85.73 87.63,84.46 93.34,84.46 98.42,79.38 98.42,75.57 100.97,73.03 100.97,71.75 104.78,67.95 104.78,62.23 104.14,61.59 109.86,55.88 110.49,55.88 117.47,48.89 117.47,43.18 118.75,41.91 118.75,40.64 120.65,38.73 120.65,36.2 119.38,34.92 v126.36,27.94
  Bottom 0.152: v126.36,27.94 125.09,27.94 122.56,25.4 130.81,17.14 131.44,17.14 133.35,15.24 133.35,14.61 v146.05,1.91
DB8-3  (via drill 0.61)
  Top 0.152: v69.22,40.64 69.22,41.91 99.06,71.75 99.69,71.75 104.78,76.84 v104.78,77.47
  Route2 0.152: v97.79,12.07 100.97,15.24 102.87,15.24 D24.V2
  Bottom 0.152: v69.22,40.64 v97.79,12.07 | v104.78,77.47 104.78,87 100.97,90.81 100.33,90.81 98.42,92.71 98.42,93.34 93.98,97.79 93.98,99.06 92.08,100.97 92.08,102.87 90.81,104.14 C25.N2
DB8-4  (via drill 0.61)
  Top 0.152: v92.08,94.62 92.08,90.81 88.27,87 87.63,87 86.36,85.73 86.36,85.09 66.67,65.41 66.67,64.77 20.95,19.05 26.04,13.97 34.29,13.97 35.56,15.24 39.37,15.24 D29.V2
  Bottom 0.152: v92.08,94.62 92.08,96.52 90.81,97.79 C25.R2
DB8-5  (via drill 0.61)
  Top 0.152: v46.35,134.62 46.99,134.62 51.44,139.06 51.44,141.61 v84.45,174.62 | v64.14,194.94 62.23,196.85 73.66,208.28 76.83,208.28 90.17,221.62 A25.V2
  Route15 0.152: v46.35,134.62 46.99,133.98 46.99,132.72 87,92.71 90.17,92.71 C25.T2
  Bottom 0.152: v64.14,194.94 v84.45,174.62
DB8-6  (via drill 0.61)
  Route2 0.152: v84.45,102.23 80.64,98.43 90.17,88.9 90.17,86.36 C25.V2 | v5.71,196.22 5.71,197.49 13.97,205.74 13.97,208.91 26.67,221.62 A30.V2
  Bottom 0.152: v84.45,102.23 83.82,102.23 66.67,119.38 66.67,131.44 57.15,140.97 55.24,140.97 45.72,150.5 45.09,150.5 38.1,157.48 38.1,158.12 36.2,160.02 35.56,160.02 15.88,179.71 15.88,186.06 v5.71,196.22
DB9  (via drill 0.61)
  Route2 0.152: v95.25,186.69 95.25,186.06 92.08,182.88 86.36,182.88 78.11,174.62 78.11,172.09 B26.N2 | v92.08,197.49 92.08,201.3 95.89,205.11 96.52,205.11 98.42,207.01 98.42,207.65 99.06,208.28 107.95,208.28 109.22,209.55 111.12,209.55 114.3,212.72 114.3,214 116.84,216.53 119.38,216.53 149.22,246.38 155.57,246.38 184.15,274.95 184.15,276.22 189.23,281.3 195.58,281.3 v203.2,288.92
  Route15 0.152: v203.2,288.92 210.82,288.92 212.72,290.83 214.63,290.83 216.53,288.92 236.22,288.92 236.85,288.29 242.57,288.29 243.21,287.65 244.47,287.65 247.01,285.11 263.52,285.11 270.51,278.13 272.42,278.13 280.04,270.51 280.04,267.97 280.67,267.33 A10.D2
  Bottom 0.152: v95.25,186.69 95.25,187.96 94.61,188.59 93.98,188.59 92.71,189.87 92.71,191.77 88.9,195.58 88.9,198.12 90.17,199.39 v92.08,197.49
DB9-0  (via drill 0.61)
  Top 0.152: v99.69,66.67 100.97,66.67 105.41,71.12 109.22,71.12 119.38,81.28 v119.38,81.92
  Route2 0.152: v64.14,107.32 77.47,120.65 77.47,123.19 C26.F2 | v133.99,75.57 135.25,75.57 146.05,86.36 146.05,87 146.69,87.63 148.59,87.63 154.31,81.92 154.94,82.55 158.75,82.55 159.38,83.19 161.93,83.19 v162.56,83.82 | v205.74,43.81 207.65,41.91 211.46,45.72 212.09,45.72 231.78,65.41 231.78,70.48 247.65,86.36 247.65,87 248.28,87.63 v249.56,87.63
  Route15 0.152: v182.88,60.32 182.88,59.69 196.85,45.72 200.03,45.72 201.93,47.62 v205.74,43.81
  Bottom 0.152: v64.14,107.32 64.77,107.32 69.85,102.23 69.85,99.7 65.41,95.25 92.08,68.58 97.79,68.58 v99.69,66.67 | v119.38,81.92 121.28,81.92 130.18,73.03 131.44,73.03 v133.99,75.57 | v162.56,83.82 162.56,83.19 170.81,74.93 170.81,72.39 v182.88,60.32 | v249.56,87.63 250.19,87.63 251.46,86.36 251.46,81.28 260.99,71.75 266.7,71.75 276.86,61.59 280.04,61.59 280.67,60.96 D10.D2
DB9-1  (via drill 0.61)
  Route2 0.152: v156.84,46.35 156.84,47.62 170.81,61.59 170.81,62.23 173.35,64.77 173.99,64.77 180.97,71.75 184.15,71.75 v187.96,75.57
  Route15 0.152: v156.84,46.35 155.57,47.62 155.57,48.89 142.88,61.59 136.53,61.59 126.36,71.75 125.73,71.75 113.03,84.46 113.03,85.09 110.49,87.63 109.86,87.63 104.14,93.34 99.06,93.34 92.08,100.33 92.08,106.05 88.27,109.86 87.63,109.86 86.36,111.12 86.36,111.76 81.28,116.84 78.11,116.84 C26.J2 | v187.96,75.57 190.5,75.57 193.68,72.39 195.58,72.39 208.91,59.05 209.55,59.05 214.63,53.98 215.26,53.98 218.44,57.15 219.71,55.88 221.62,55.88 222.88,57.15 221.62,58.42 219.07,58.42 217.81,59.69 D15.D2
DB9-2  (via drill 0.61)
  Route2 0.152: v142.88,55.24 146.05,55.24 149.86,59.05 153.03,59.05 153.67,59.69 D20.D2
  Bottom 0.152: v142.88,55.24 132.72,65.41 132.72,66.04 115.57,83.19 114.3,83.19 113.03,84.46 113.03,85.09 110.49,87.63 109.86,87.63 107.31,90.17 107.31,90.81 100.97,97.16 100.33,97.16 99.06,98.43 99.06,99.06 92.08,106.05 86.36,106.05 85.72,106.68 80.01,106.68 78.11,108.59 78.11,110.49 C26.L2
DB9-3  (via drill 0.61)
  Top 0.152: v67.94,85.73 79.38,97.16 v79.38,101.6
  Bottom 0.152: v67.94,85.73 90.17,63.5 90.17,60.96 D25.D2 | v79.38,101.6 79.38,102.87 78.11,104.14 C26.N2
DB9-4
  Top 0.152: D30.D2 26.67,59.69 26.67,55.88 25.4,54.61 25.4,53.34 27.3,51.43 44.45,68.58 44.45,69.85 57.15,82.55 59.05,82.55 73.66,97.16 76.83,97.16 77.47,97.79 C26.R2
DB9-5  (via drill 0.61)
  Top 0.152: v27.3,210.82 27.3,213.36 69.22,255.27 69.85,255.27 76.2,261.62 76.2,262.89 76.83,263.52 76.83,265.43 77.47,266.06 A26.D2
  Route2 0.152: v1.91,175.9 3.17,177.16 3.17,182.88 26.04,205.74 26.04,209.55 v27.3,210.82
  Route15 0.152: v29.84,143.51 56.52,116.84 56.52,115.57 57.78,114.3 58.42,114.3 77.47,95.25 77.47,92.71 C26.T2
  Bottom 0.152: v29.84,143.51 27.3,143.51 20.32,150.5 19.68,150.5 3.17,167 3.17,174.62 v1.91,175.9
DB9-6  (via drill 0.61)
  Route2 0.152: v44.45,220.98 50.16,215.27 42.55,207.65 41.91,207.65 41.27,207.01 41.27,206.38 40.01,205.11 38.73,205.11 28.57,194.94 v28.57,165.74
  Route15 0.152: v28.57,165.74 28.57,163.83 16.51,151.77 24.77,143.51 24.77,141.61 41.27,125.09 41.27,113.03 48.26,106.05 54.61,106.05 73.66,87 76.83,87 77.47,86.36 C26.V2
  Bottom 0.152: v44.45,220.98 15.88,249.56 15.88,260.99 14.61,262.25 14.61,266.06 A31.D2
DB10  (via drill 0.61)
  Top 0.152: v100.33,145.41 107.31,145.41 110.49,148.59 115.57,148.59 124.46,157.48 130.18,157.48 137.16,164.47 137.16,166.37 135.25,168.28 143.51,176.53 143.51,178.44 144.78,179.71 145.41,179.71 146.05,180.34 146.05,182.88 144.15,184.78 v146.05,186.69
  Route2 0.152: v146.05,186.69 147.32,187.96 148.59,187.96 159.38,198.75 161.93,198.75 163.19,197.49 163.83,198.12 164.47,198.12 171.45,205.11 171.45,210.82 190.5,229.87 191.77,229.87 193.68,231.78 193.68,233.05 200.66,240.03 205.74,240.03 206.38,240.66 206.38,245.75 219.07,258.44 225.43,258.44 228.6,261.62 234.31,261.62 251.46,278.76 255.27,278.76 257.18,280.67 v266.06,280.67
  Route15 0.152: v100.33,145.41 81.28,164.47 78.11,164.47 B26.R2
  Bottom 0.152: v266.06,280.67 267.97,280.67 270.51,278.13 272.42,278.13 281.31,269.24 281.31,268.6 282.57,267.33 282.57,265.43 283.85,264.16 A10.E2
DB10-0  (via drill 0.61)
  Top 0.152: v266.7,12.07 257.18,12.07 256.54,11.43 248.92,11.43 241.94,4.45 238.76,4.45 238.12,3.81 233.04,3.81 v232.41,3.18
  Route2 0.152: v292.1,41.27 292.1,39.37 293.37,38.1 267.33,12.07 v266.7,12.07 | v165.1,77.47 165.1,76.2 161.93,73.03 v155.57,73.03 | v85.09,141.61 80.64,141.61 74.3,135.25 73.66,135.25 66.67,128.27 66.67,125.73 65.41,124.46 C27.F2
  Route15 0.152: v232.41,3.18 231.14,1.91 229.24,1.91 223.52,7.62 222.25,7.62 210.19,19.69 209.55,19.69 208.28,20.95 208.28,22.23 196.22,34.29 196.22,34.92 188.59,42.55 187.96,42.55 173.99,56.52 173.99,57.78 175.9,59.69 v176.53,59.05 | v155.57,73.03 155.57,73.66 142.24,87 136.53,87 120.65,102.87 120.65,104.14 117.47,107.32 117.47,113.03 104.78,125.73 104.78,126.37 103.5,127.64 102.23,127.64 88.27,141.61 v85.09,141.61
  Bottom 0.152: v292.1,41.27 291.46,41.91 292.74,43.18 292.74,44.45 292.1,45.09 292.1,46.35 284.48,53.98 284.48,56.52 D10.E2 | v176.53,59.05 176.53,60.32 168.28,68.58 168.28,74.3 v165.1,77.47
DB10-1  (via drill 0.61)
  Top 0.152: v205.1,71.12 205.1,70.48 199.39,64.77 194.31,64.77 v193.04,63.5 | v96.52,134.62 91.44,134.62 79.38,122.56 73.03,122.56 69.85,119.38 66.67,119.38 65.41,118.11 C27.J2
  Route15 0.152: v205.1,71.12 206.38,69.85 206.38,68.58 210.19,64.77 210.19,63.5 211.46,62.23 212.09,62.23 216.53,57.78 220.34,57.78 D15.E2 | v193.04,63.5 191.77,63.5 142.88,112.4 137.16,112.4 127.64,121.92 127.64,122.56 126.36,123.83 125.73,123.19 117.47,131.44 v114.3,131.44
  Bottom 0.152: v114.3,131.44 109.86,127 101.6,135.25 98.42,135.25 97.16,133.98 v96.52,134.62
DB10-2  (via drill 0.61)
  Top 0.152: v54.61,104.14 60.33,109.86 62.23,109.86 62.87,110.49 64.77,110.49 C27.L2 | v133.35,25.4 134.62,25.4 158.75,49.53 158.75,53.34 156.21,55.88 156.84,56.52 D20.E2
  Route15 0.152: v54.61,104.14 55.88,104.14 73.66,86.36 73.66,80.65 99.06,55.24 104.14,55.24 v106.68,52.7
  Bottom 0.152: v106.68,52.7 107.95,51.43 107.95,48.89 106.68,47.62 116.2,38.1 116.84,38.1 118.11,36.83 117.47,36.2 118.75,34.92 121.92,38.1 128.27,31.75 128.27,31.12 133.35,26.04 v133.35,25.4
DB10-3  (via drill 0.61)
  Top 0.152: v59.05,93.98 59.05,95.89 64.14,100.97 64.14,103.51 64.77,104.14 C27.N2
  Bottom 0.152: v59.05,93.98 59.69,93.98 66.67,87 67.94,87 69.22,85.73 69.22,85.09 93.34,60.96 93.34,57.78 D25.E2
DB10-4
  Top 0.152: D30.E2 30.48,57.78 30.48,60.32 41.27,71.12 42.55,71.12 47.62,76.2 47.62,78.11 64.14,94.62 64.14,97.16 64.77,97.79 C27.R2
DB10-5  (via drill 0.61)
  Top 0.152: v54.61,82.55 55.88,83.82 59.69,83.82 64.77,88.9 64.77,91.44 C27.T2
  Route2 0.152: v11.43,198.12 12.7,198.12 76.2,261.62 79.38,261.62 80.64,262.89 A26.E2
  Route15 0.152: v54.61,82.55 46.35,82.55 28.57,100.33 28.57,106.05 6.35,128.27 6.35,129.54 5.71,130.18 5.71,130.81 11.43,136.53 8.89,139.06 8.89,149.86 27.3,168.28 15.88,179.71 15.88,191.14 14.61,192.41 14.61,193.68 12.06,196.22 12.06,197.49 v11.43,198.12
DB10-6  (via drill 0.61)
  Route2 0.152: v93.34,124.46 94.61,123.19 93.34,121.92 92.08,121.92 66.67,96.52 66.67,87.63 65.41,86.36 C27.V2
  Route15 0.152: v41.27,231.14 41.27,223.52 41.91,222.89 41.91,220.98 34.92,214 34.92,210.82 38.73,207.01 38.73,206.38 41.27,203.84 41.27,198.12 53.98,185.42 53.98,172.72 66.67,160.02 66.67,151.77 82.55,135.89 82.55,135.25 v93.34,124.46
  Bottom 0.152: v41.27,231.14 41.27,236.22 17.78,259.71 17.78,262.89 A31.E2
DB11  (via drill 0.61)
  Top 0.152: v182.88,212.09 185.42,212.09 v215.26,241.94 | v272.42,241.94 278.13,247.65 278.76,247.65 280.04,248.92 280.04,252.09 278.13,254 279.4,255.27 282.57,255.27 283.85,256.54 A10.H2
  Route2 0.152: v96.52,145.41 99.06,145.41 123.83,170.18 130.18,170.18 140.34,180.34 140.34,181.61 137.79,184.15 139.7,186.06 140.34,186.06 142.24,187.96 142.24,188.59 153.03,199.39 153.03,201.93 151.76,203.2 156.21,207.65 158.12,207.65 160.02,209.55 165.1,209.55 v167.64,212.09 | v228.6,233.05 228.6,235.59 232.41,239.4 234.95,239.4 236.22,238.12 250.82,252.73 252.09,252.73 v258.44,259.08
  Route15 0.152: v96.52,145.41 91.44,150.5 88.9,150.5 81.28,158.12 78.11,158.12 B26.T2
  Bottom 0.152: v182.88,212.09 v167.64,212.09 | v215.26,241.94 217.17,243.84 224.16,236.86 224.79,236.86 v228.6,233.05 | v258.44,259.08 259.71,259.08 269.88,248.92 269.88,243.84 271.78,241.94 v272.42,241.94
DB11-0  (via drill 0.61)
  Top 0.152: v278.13,46.35 278.13,46.99 280.04,48.89 282.57,48.89 283.85,50.16 D10.H2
